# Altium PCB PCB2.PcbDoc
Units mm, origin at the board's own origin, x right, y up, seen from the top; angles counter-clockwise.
Board outline 150 x 51.5 mm, 2 copper layers (Top Layer, Bottom Layer), stack 1.571 mm thick; 8 components, 0 nets, 8 pads, 0 vias.
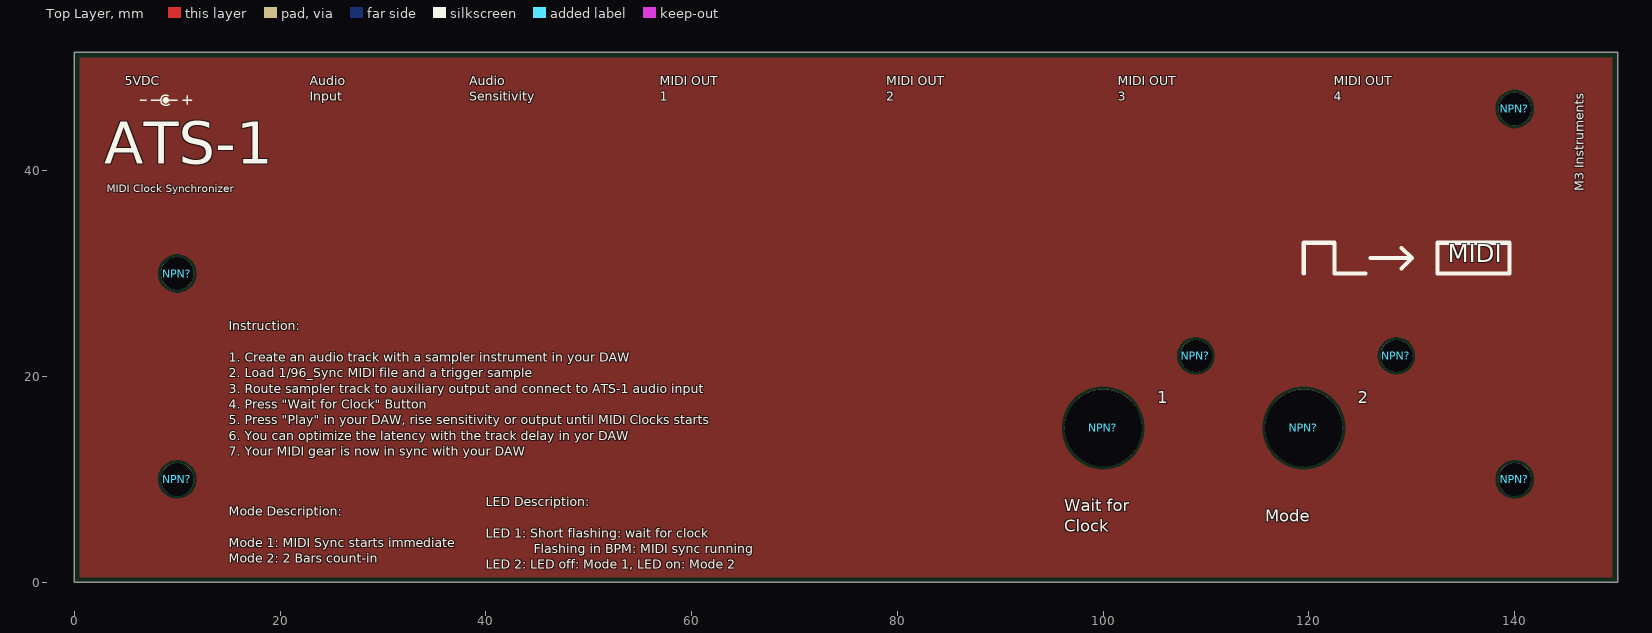
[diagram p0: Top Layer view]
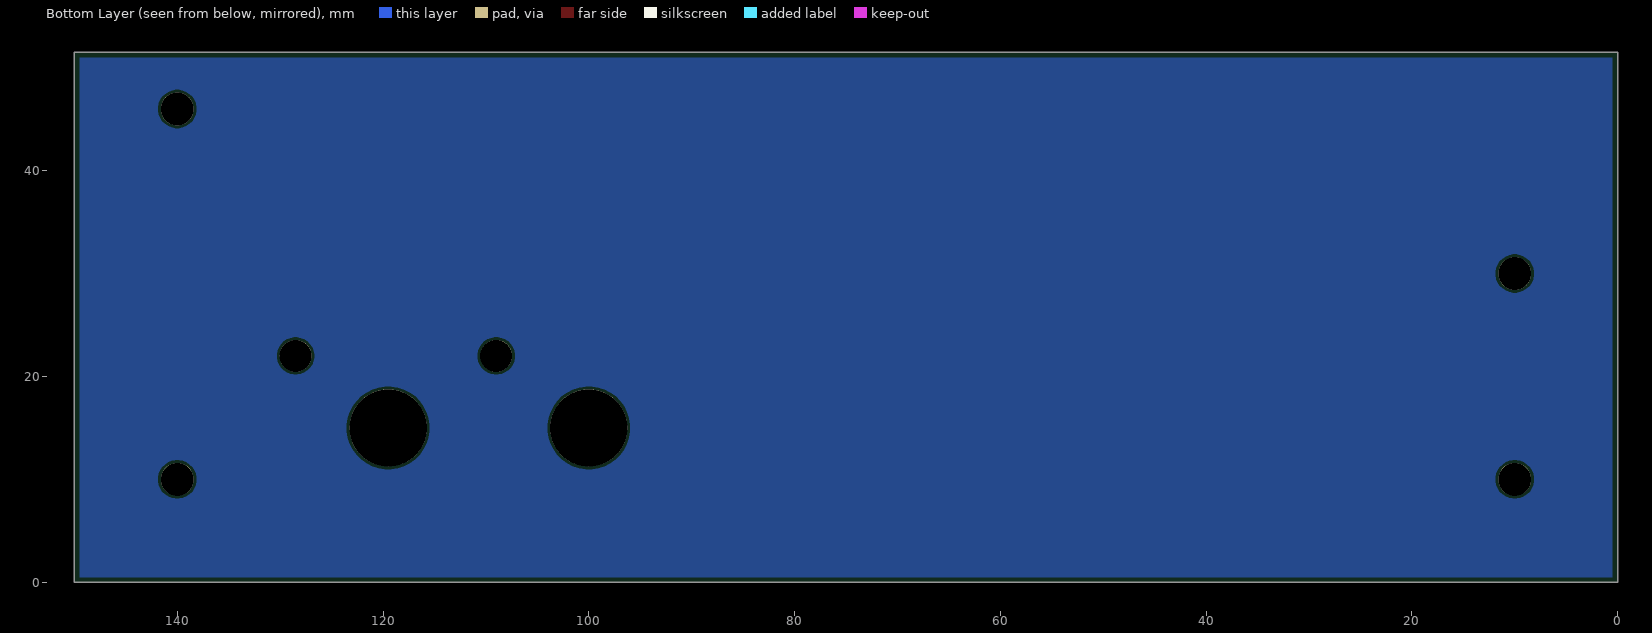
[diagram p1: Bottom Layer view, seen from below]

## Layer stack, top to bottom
Top Solder: solder mask 0.0102, Solder Resist, Dk 3.5
Top Layer: signal copper 0.0356
Dielectric 1: dielectric 1.5, FR-4, Dk 4.8
Bottom Layer: signal copper 0.0356
Bottom Solder: solder mask 0.0102, Solder Resist, Dk 3.5

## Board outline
0,0 150,0 150,51.5 0,51.5

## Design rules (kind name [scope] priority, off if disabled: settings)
Clearance [All] p1: gap=0.254 ignorepadtopadclearanceinfootprint=FALSE except(0: Arc-Hole Track-Hole SMDPad-Hole THPad-Hole Via-Hole Fill-Hole Poly-Hole Region-Hole Text-Hole)
PolygonConnect [All] p1: connectstyle=Relief reliefconductorwidth=0.254 reliefentries=4 polygonreliefangle="90 Angle" airgapwidth=0.254
RoomDefinition Sheet1 [InComponentClass('Sheet1')] p1: confinementstyle=ConfineIn formatcopy=TRUE lockcomponents=FALSE outline 139.5,2 169,2 169,8.5 139.5,8.5
RoutingVias [All] p1: holewidth=0.711 width=1.27 viastyle="Through Hole" minholewidth=0.711 minwidth=1.27 maxholewidth=0.711 maxwidth=1.27
SolderMaskExpansion [All] p1: expansion=0.102 istentingtop=FALSE
Width [All] p1: maxlimit=0.254 minlimit=0.254 preferedwidth=0.254
30 further rules are at their usual default settings.

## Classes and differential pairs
component class Sheet1: NPN?

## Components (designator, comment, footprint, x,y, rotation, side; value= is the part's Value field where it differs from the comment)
NPN? "NPN_3.2mm" HOLE_NPH_3.2_M3#1 7.5,41.5 r90 top
NPN? "NPN_3.2mm" HOLE_NPH_3.2_M3#2 7.5,7 r90 top
NPN? "NPN_3.2mm" HOLE_NPH_3.2_M3#3 134.5,7 r90 top
NPN? "NPN_3.2mm" HOLE_NPH_3.2_M3#4 134.5,41.5 r90 top
NPN? "NPN_3.1mm" HOLE_NPH_3.1_LED_3mm 109,22 r90 top
NPN? "NPN_7.5mm" HOLE_NPH_7.5_F01 119.5,15 r0 top
NPN? "NPN_3.1mm" HOLE_NPH_3.1_LED_3mm 128.5,22 r90 top
NPN? "NPN_7.5mm" HOLE_NPH_7.5_F01 100,15 r0 top

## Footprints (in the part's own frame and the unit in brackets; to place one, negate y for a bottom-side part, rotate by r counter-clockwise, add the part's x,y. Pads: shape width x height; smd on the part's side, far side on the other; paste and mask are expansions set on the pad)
HOLE_NPH_3.1_LED_3mm [mm]
  round 3.1 hole 3.1 unplated: 8(0,0)
HOLE_NPH_3.2_M3#1 [mm]
  round 3.2 hole 3.2 unplated: 8(-11.5,-2.5)
HOLE_NPH_3.2_M3#2 [mm]
  round 3.2 hole 3.2 unplated: 8(3,-2.5)
HOLE_NPH_3.2_M3#3 [mm]
  round 3.2 hole 3.2 unplated: 8(3,-5.5)
HOLE_NPH_3.2_M3#4 [mm]
  round 3.2 hole 3.2 unplated: 8(4.5,-5.5)
HOLE_NPH_7.5_F01 [mm]
  round 7.5 hole 7.5 unplated: 1(0,0)

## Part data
NPN? NPN? NPN? NPN?: library part NPH_3.2mm_M3
NPN? NPN?: library part NPH_3.1mm_LED_3mm
NPN? NPN?: library part NPH_7.5mm_F01

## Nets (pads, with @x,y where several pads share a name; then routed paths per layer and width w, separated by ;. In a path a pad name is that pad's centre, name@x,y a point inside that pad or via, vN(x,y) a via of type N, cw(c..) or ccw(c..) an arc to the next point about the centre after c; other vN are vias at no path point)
pads on no net: NPN?.1 NPN?.8

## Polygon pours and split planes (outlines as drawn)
no net on Bottom Layer "NONET_L02_P001" (solid, pour order 1): 0.5,51 149.5,51 149.5,0.5 0.5,0.5
no net on Top Layer "NONET_L01_P000" (solid, pour order 0): 0.5,51 149.5,51 149.5,0.5 0.5,0.5

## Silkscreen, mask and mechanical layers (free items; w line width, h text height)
Top Overlay:
  circle w0.4: c8.888,46.848 r0.1
  lines w0.15: 6.388,46.848 6.991,46.848 ; 7.491,46.848 8.388,46.848 ; 8.888,46.848 9.991,46.848 ; 9.111,47.295 ccw(c8.888,46.848) 9.218,46.473 ; 10.535,46.848 11.391,46.848 ; 10.991,46.448 10.991,47.295
  lines w0.4: 119.498,30 119.498,33 ; 119.724,33 119.499,33 122.498,33 122.498,30 125.498,30 ; 125.998,31.5 129.999,31.5 ; 128.999,30.5 129.999,31.5 ; 128.999,32.5 129.999,31.5 ; 139.498,33 139.498,30 132.5,30 132.5,33 136.75,33 139.5,33
  text "5VDC" at 4.897,48 h1.52
  text "Audio  / Input" at 22.897,46.5 h1.52
  text "Audio  / Sensitivity" at 38.397,46.5 h1.52
  text "MIDI OUT  / 1" at 56.897,46.5 h1.52
  text "MIDI OUT  / 2" at 78.897,46.5 h1.52
  text "MIDI OUT  / 3" at 101.397,46.5 h1.52
  text "MIDI OUT  / 4" at 122.397,46.5 h1.52
  text "ATS-1" at 2.9,39.3 h7
  text "M3 Instruments" at 146.982,38 h1.5 r90
  text "MIDI Clock Synchronizer" at 3.154,37.904 h0.75
  text "MIDI" at 133.5,30.5 h3
  text "1" at 105.234,17 h2
  text "2" at 124.734,17 h2
  text "Instruction: /  / 1. Create an audio track with a sampler instrument in your DAW / 2. Load 1/96_Sync MIDI file and a trigger sample / 3. Route sampler track to auxiliary output and connect to ATS-1 audio input / 4. Press \"Wait for Clock\" Button / 5. Press \"Play\" in your DAW, rise sensitivity or output until MIDI Clocks starts / 6. You can optimize the latency with the track delay in yor DAW / 7. Your MIDI gear is now in sync with your DAW" at 15,12 h1.52
  text "Mode" at 115.734,5.5 h2
  text "Wait for  / Clock" at 96.234,4.5 h2
  text "Mode Description: /  / Mode 1: MIDI Sync starts immediate / Mode 2: 2 Bars count-in" at 15,1.578 h1.52
  text "LED Description: /  / LED 1: Short flashing: wait for clock /             Flashing in BPM: MIDI sync running / LED 2: LED off: Mode 1, LED on: Mode 2" at 40,1 h1.52
Top Solder:
  circle w0.4: c79.625,13.3 r5.442
  lines w0.05: 117.957,51 145,51 145,50
  lines w0.2: 23.5,37 138,37 ; 23.5,38 137,38 ; 23.5,39 136,39 ; 23.5,40 135,40 ; 23.5,41 134,41 ; 23.5,42 132.424,42 ; 23.5,43 132,43 ; 23.5,44 131,44
  lines w0.4: 132.424,42 133,41.424
  lines w0.8: 1.5,26.632 149,26.632 ; 1.5,35.848 80.527,35.848 71.311,26.632 66.717,26.632 57.792,35.557 ; 1.5,41 1.5,45.1 28.1,45.1 ; 12.962,35.557 21.887,26.632 25.887,26.632 34.812,35.557 ; 17.854,45.1 129.6,45.1 138.7,36 ; 23.492,44.9 23.5,36 ; 35.377,35.557 44.302,26.632 48.302,26.632 57.227,35.557 ; 66.697,26.652 69,26.652 69,1.512 68.717,1.229 ; 80.207,35.557 89.132,26.632 93.132,26.632 102.057,35.557 ; 80.5,35.848 149,35.848 ; 86.863,1.237 91,1.237 ; 102.622,35.557 111.422,26.757 ; 134.92,1.2 149,1.2 149,50 1.5,50 1.5,1.2 137.2,1.2 ; 136.79,37.91 136.88,37.82
  text "3" at 83.12,15.797 h5 r180
  text "3" at 76.15,10.825 h5
Bottom Solder:
  circle w2: c10,10 r2.55
  circle w2: c10,30 r2.55
  circle w2: c140,10 r2.55
  circle w2: c140,46 r2.55
Mechanical 1:
  circle w0.254: c5,5 r0.5
  lines w0.05: 4,5 6,5 ; 5,4 5,6
Mechanical 2:
  lines w0.05: 0,0 150,0 150,51.5 0,51.5 0,0
  lines w0.17: 0,51.5 0,51.5 ; 150,0 150,0 ; 150,51.5 150,51.5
